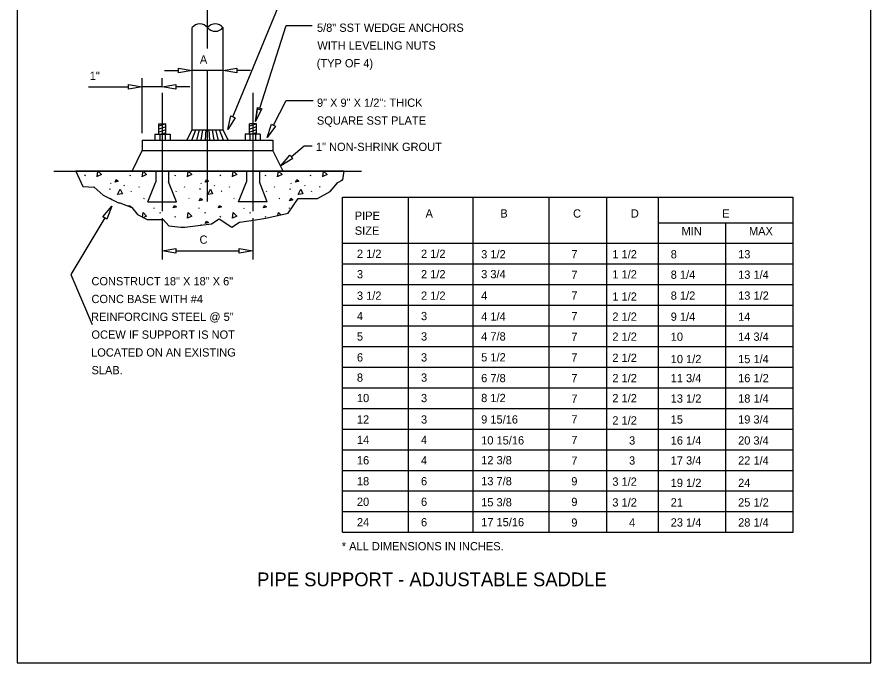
# Model space of a CAD drawing. Extents: x 2147138 to 2147698, y 2147153 to 2147515.
# Drawn here: x 2147297.9 to 2147422.1, y 2147351.3 to 2147445.1 of the extents above; entities that cross this region are included whole.
import ezdxf

# ---------------------------------------------------------------- set-up
doc = ezdxf.new("R2010")
doc.units = 0
for name, color, linetype in [('1', 7, 'Continuous'), ('D-PIPE-CNTR', 7, 'Continuous'), ('G-ANNO-TABL', 7, 'Continuous'), ('G-ANNO-TEXT-LW10', 7, 'Continuous'), ('G-ANNO-TITL', 7, 'Continuous'), ('G-DETL-HIDD', 7, 'Continuous'), ('G-DETL-LW10', 7, 'Continuous'), ('G-DETL-LW20', 7, 'Continuous'), ('G-DETL-PATT', 7, 'Continuous'), ('PATTERN_CLASS', 7, 'Continuous')]:
    doc.layers.add(name, color=color, linetype=linetype)

msp = doc.modelspace()

# ---------------------------------------------------------------- linework, layer by layer
at = {"layer": '1'}
for p, q in [((2147307.76, 2147422.09), (2147307.82, 2147422.23)), ((2147309.53, 2147421.94), (2147309.65, 2147422.77)), ((2147310.17, 2147422.24), (2147309.55, 2147421.95)), ((2147309.65, 2147422.77), (2147310.17, 2147422.24)), ((2147312.11, 2147422.69), (2147312.14, 2147422.77)), ((2147314.32, 2147422.09), (2147314.38, 2147422.23)), ((2147316.09, 2147421.94), (2147316.21, 2147422.77)), ((2147316.73, 2147422.24), (2147316.11, 2147421.95)), ((2147316.21, 2147422.77), (2147316.73, 2147422.24)), ((2147320.88, 2147422.09), (2147320.94, 2147422.23)), ((2147322.66, 2147421.94), (2147322.77, 2147422.77)), ((2147323.29, 2147422.24), (2147322.67, 2147421.95)), ((2147322.77, 2147422.77), (2147323.29, 2147422.24)), ((2147325.23, 2147422.69), (2147325.27, 2147422.77)), ((2147327.44, 2147422.09), (2147327.5, 2147422.23)), ((2147329.22, 2147421.94), (2147329.33, 2147422.77)), ((2147329.85, 2147422.24), (2147329.23, 2147421.95)), ((2147329.34, 2147422.77), (2147329.85, 2147422.24)), ((2147334.01, 2147422.09), (2147334.06, 2147422.23)), ((2147335.78, 2147421.94), (2147335.89, 2147422.77)), ((2147336.42, 2147422.24), (2147335.79, 2147421.95)), ((2147335.9, 2147422.77), (2147336.42, 2147422.24)), ((2147338.35, 2147422.69), (2147338.39, 2147422.77)), ((2147340.57, 2147422.09), (2147340.63, 2147422.23)), ((2147342.34, 2147421.94), (2147342.45, 2147422.77)), ((2147342.98, 2147422.24), (2147342.35, 2147421.95)), ((2147342.46, 2147422.77), (2147342.98, 2147422.24)), ((2147344.92, 2147422.69), (2147344.95, 2147422.77)), ((2147311.47, 2147421.06), (2147311.53, 2147420.97)), ((2147312.14, 2147421.16), (2147312.31, 2147421.53)), ((2147312.6, 2147421.31), (2147312.14, 2147421.16)), ((2147312.31, 2147421.53), (2147312.6, 2147421.31)), ((2147324.59, 2147421.06), (2147324.65, 2147420.97)), ((2147325.26, 2147421.16), (2147325.43, 2147421.53)), ((2147325.73, 2147421.31), (2147325.26, 2147421.16)), ((2147325.43, 2147421.53), (2147325.73, 2147421.31)), ((2147331.15, 2147421.06), (2147331.18, 2147421.03)), ((2147337.71, 2147421.06), (2147337.77, 2147420.97)), ((2147338.38, 2147421.16), (2147338.56, 2147421.53)), ((2147338.85, 2147421.31), (2147338.38, 2147421.16)), ((2147338.56, 2147421.53), (2147338.85, 2147421.31)), ((2147344.28, 2147421.06), (2147344.33, 2147420.97)), ((2147345.06, 2147421.4), (2147345.12, 2147421.53)), ((2147345.12, 2147421.53), (2147345.19, 2147421.47)), ((2147309.08, 2147420.41), (2147309.14, 2147420.54)), ((2147311.36, 2147420.1), (2147311.42, 2147420.23)), ((2147312.5, 2147419.37), (2147312.89, 2147420.12)), ((2147312.89, 2147420.12), (2147313.2, 2147419.43)), ((2147313.43, 2147420.69), (2147313.49, 2147420.6)), ((2147314.47, 2147419.77), (2147314.53, 2147419.9)), ((2147315.65, 2147420.41), (2147315.71, 2147420.54)), ((2147321.03, 2147419.77), (2147321.09, 2147419.9)), ((2147322.21, 2147420.41), (2147322.27, 2147420.54)), ((2147324.48, 2147420.1), (2147324.54, 2147420.23)), ((2147325.62, 2147419.37), (2147326.02, 2147420.12)), ((2147326.02, 2147420.12), (2147326.32, 2147419.43)), ((2147326.55, 2147420.69), (2147326.61, 2147420.6)), ((2147327.59, 2147419.77), (2147327.65, 2147419.9)), ((2147328.77, 2147420.41), (2147328.83, 2147420.54)), ((2147334.15, 2147419.77), (2147334.21, 2147419.9)), ((2147335.33, 2147420.41), (2147335.39, 2147420.54)), ((2147337.6, 2147420.1), (2147337.66, 2147420.23)), ((2147338.75, 2147419.37), (2147339.14, 2147420.12)), ((2147339.14, 2147420.12), (2147339.45, 2147419.43)), ((2147339.68, 2147420.69), (2147339.74, 2147420.6)), ((2147340.71, 2147419.77), (2147340.77, 2147419.9)), ((2147341.89, 2147420.41), (2147341.95, 2147420.54)), ((2147311.41, 2147418.77), (2147311.43, 2147418.82)), ((2147311.43, 2147418.82), (2147311.65, 2147418.65)), ((2147313.2, 2147419.43), (2147312.51, 2147419.37)), ((2147316.29, 2147418.83), (2147316.35, 2147418.75)), ((2147322.85, 2147418.83), (2147322.91, 2147418.75)), ((2147324.38, 2147418.45), (2147324.55, 2147418.82)), ((2147324.84, 2147418.6), (2147324.38, 2147418.45)), ((2147324.55, 2147418.82), (2147324.84, 2147418.6)), ((2147326.32, 2147419.43), (2147325.64, 2147419.37)), ((2147329.41, 2147418.83), (2147329.47, 2147418.75)), ((2147335.97, 2147418.83), (2147336.03, 2147418.75)), ((2147337.5, 2147418.45), (2147337.68, 2147418.82)), ((2147337.97, 2147418.6), (2147337.5, 2147418.45)), ((2147337.68, 2147418.82), (2147337.97, 2147418.6)), ((2147339.45, 2147419.43), (2147338.76, 2147419.37)), ((2147314.14, 2147417.63), (2147314.21, 2147417.78)), ((2147314.21, 2147417.78), (2147314.5, 2147417.56)), ((2147314.5, 2147417.56), (2147314.39, 2147417.52)), ((2147317.76, 2147417.44), (2147317.77, 2147417.31)), ((2147320.59, 2147417.41), (2147320.77, 2147417.78)), ((2147321.06, 2147417.56), (2147320.59, 2147417.41)), ((2147320.77, 2147417.78), (2147321.06, 2147417.56)), ((2147324.32, 2147417.44), (2147324.34, 2147417.31)), ((2147327.16, 2147417.41), (2147327.33, 2147417.78)), ((2147327.62, 2147417.56), (2147327.16, 2147417.41)), ((2147327.33, 2147417.78), (2147327.62, 2147417.56)), ((2147330.88, 2147417.44), (2147330.9, 2147417.31)), ((2147333.72, 2147417.41), (2147333.89, 2147417.78)), ((2147334.18, 2147417.56), (2147333.72, 2147417.41)), ((2147333.89, 2147417.78), (2147334.18, 2147417.56)), ((2147337.45, 2147417.44), (2147337.46, 2147417.31)), ((2147316.11, 2147416.07), (2147316.21, 2147416.75)), ((2147316.21, 2147416.75), (2147316.73, 2147416.21)), ((2147316.73, 2147416.21), (2147316.26, 2147415.99)), ((2147318.67, 2147416.66), (2147318.73, 2147416.79)), ((2147320.88, 2147416.07), (2147320.94, 2147416.2)), ((2147322.66, 2147415.92), (2147322.77, 2147416.75)), ((2147323.29, 2147416.21), (2147322.67, 2147415.92)), ((2147322.77, 2147416.75), (2147323.29, 2147416.21)), ((2147325.23, 2147416.66), (2147325.29, 2147416.79)), ((2147327.44, 2147416.07), (2147327.5, 2147416.2)), ((2147329.22, 2147415.92), (2147329.33, 2147416.75)), ((2147329.85, 2147416.21), (2147329.23, 2147415.92)), ((2147329.33, 2147416.75), (2147329.85, 2147416.21)), ((2147331.79, 2147416.66), (2147331.85, 2147416.79)), ((2147334.01, 2147416.07), (2147334.06, 2147416.2)), ((2147335.83, 2147416.31), (2147335.89, 2147416.75)), ((2147335.89, 2147416.75), (2147336.23, 2147416.4)), ((2147324.59, 2147415.03), (2147324.65, 2147414.94)), ((2147325.26, 2147415.13), (2147325.43, 2147415.5)), ((2147325.73, 2147415.28), (2147325.26, 2147415.13)), ((2147325.43, 2147415.5), (2147325.73, 2147415.28))]:
    msp.add_line(p, q, dxfattribs=at)
at = {"layer": 'D-PIPE-CNTR'}
for p, q in [((2147325.59, 2147440.58), (2147325.59, 2147449.16)), ((2147325.59, 2147418.35), (2147325.59, 2147437.38)), ((2147318.99, 2147434.15), (2147318.99, 2147416.93)), ((2147332.18, 2147434.15), (2147332.18, 2147416.93))]:
    msp.add_line(p, q, dxfattribs=at)
at = {"layer": 'G-ANNO-TABL'}
for p, q in [((2147345.2, 2147418.97), (2147410.75, 2147418.97)), ((2147345.2, 2147370.26), (2147345.2, 2147418.97)), ((2147354.81, 2147370.26), (2147354.81, 2147418.97)), ((2147364.23, 2147370.26), (2147364.23, 2147418.97)), ((2147375.25, 2147370.26), (2147375.25, 2147418.97)), ((2147383.65, 2147370.26), (2147383.65, 2147418.97)), ((2147391.15, 2147370.26), (2147391.15, 2147418.97)), ((2147410.75, 2147370.26), (2147410.75, 2147418.97)), ((2147391.15, 2147415.26), (2147410.75, 2147415.26)), ((2147345.2, 2147412.26), (2147410.75, 2147412.26)), ((2147345.2, 2147409.26), (2147410.75, 2147409.26)), ((2147345.2, 2147406.26), (2147410.75, 2147406.26)), ((2147345.2, 2147403.26), (2147410.75, 2147403.26)), ((2147345.2, 2147400.26), (2147410.75, 2147400.26)), ((2147345.2, 2147397.26), (2147410.75, 2147397.26)), ((2147345.2, 2147394.26), (2147410.75, 2147394.26)), ((2147345.2, 2147391.26), (2147410.75, 2147391.26)), ((2147345.2, 2147388.26), (2147410.75, 2147388.26)), ((2147345.2, 2147385.26), (2147410.75, 2147385.26)), ((2147345.2, 2147382.26), (2147410.75, 2147382.26)), ((2147345.2, 2147379.26), (2147410.75, 2147379.26)), ((2147345.2, 2147376.26), (2147410.75, 2147376.26)), ((2147345.2, 2147373.26), (2147410.75, 2147373.26)), ((2147345.2, 2147370.26), (2147410.75, 2147370.26))]:
    msp.add_line(p, q, dxfattribs=at)
at = {"layer": 'G-ANNO-TEXT-LW10'}
for p, q in [((2147329.28, 2147430.64), (2147337.01, 2147449.42)), ((2147333.17, 2147431.89), (2147337.01, 2147443.92)), ((2147337.01, 2147443.92), (2147340.78, 2147443.92)), ((2147319.34, 2147437.38), (2147321.34, 2147437.38)), ((2147327.84, 2147437.38), (2147323.34, 2147437.38)), ((2147331.84, 2147437.38), (2147329.84, 2147437.38)), ((2147316.1, 2147428.27), (2147316.1, 2147436.29)), ((2147318.99, 2147435.15), (2147318.99, 2147436.29)), ((2147308.25, 2147435.01), (2147314.1, 2147435.01)), ((2147318.99, 2147435.01), (2147316.1, 2147435.01)), ((2147322.99, 2147435.01), (2147320.99, 2147435.01)), ((2147335.16, 2147429.43), (2147337.01, 2147433.02)), ((2147337.01, 2147433.02), (2147340.97, 2147433.02)), ((2147337.76, 2147424.83), (2147339.63, 2147426.45)), ((2147339.63, 2147426.45), (2147340.79, 2147426.45)), ((2147310.65, 2147415.96), (2147305.68, 2147407.72)), ((2147318.99, 2147415.93), (2147318.99, 2147409.89)), ((2147332.18, 2147415.93), (2147332.18, 2147409.89)), ((2147400.95, 2147370.26), (2147400.95, 2147415.26)), ((2147320.99, 2147411.17), (2147330.18, 2147411.17)), ((2147305.68, 2147407.72), (2147308.81, 2147400.45))]:
    msp.add_line(p, q, dxfattribs=at)
for points in [[(2147321.34, 2147437.71), (2147323.34, 2147437.38), (2147321.34, 2147437.05)], [(2147329.84, 2147437.05), (2147327.84, 2147437.38), (2147329.84, 2147437.71)], [(2147314.1, 2147435.35), (2147316.1, 2147435.01), (2147314.1, 2147434.68)], [(2147320.99, 2147434.68), (2147318.99, 2147435.01), (2147320.99, 2147435.35)], [(2147329.59, 2147430.51), (2147328.52, 2147428.79), (2147328.97, 2147430.77)], [(2147333.49, 2147431.79), (2147332.56, 2147429.98), (2147332.85, 2147431.99)], [(2147333.39, 2147431.6), (2147332.82, 2147431.78), (2147332.56, 2147429.98)], [(2147335.46, 2147429.27), (2147334.25, 2147427.65), (2147334.87, 2147429.58)], [(2147337.98, 2147424.58), (2147336.25, 2147423.52), (2147337.54, 2147425.08)], [(2147310.37, 2147416.13), (2147311.68, 2147417.67), (2147310.94, 2147415.79)], [(2147320.99, 2147410.84), (2147318.99, 2147411.17), (2147320.99, 2147411.51)], [(2147330.18, 2147411.51), (2147332.18, 2147411.17), (2147330.18, 2147410.84)]]:
    msp.add_lwpolyline(points, close=True, dxfattribs=at)
at = {"layer": 'G-DETL-HIDD'}
for p, q in [((2147318.05, 2147422.77), (2147318.05, 2147421.21)), ((2147319.93, 2147422.77), (2147319.93, 2147421.21)), ((2147331.25, 2147422.77), (2147331.25, 2147421.21)), ((2147333.12, 2147422.77), (2147333.12, 2147421.21)), ((2147316.89, 2147418.29), (2147318.05, 2147421.21)), ((2147321.09, 2147418.29), (2147319.93, 2147421.21)), ((2147330.08, 2147418.29), (2147331.25, 2147421.21)), ((2147334.28, 2147418.29), (2147333.12, 2147421.21)), ((2147316.89, 2147418.29), (2147321.09, 2147418.29)), ((2147334.28, 2147418.29), (2147330.08, 2147418.29))]:
    msp.add_line(p, q, dxfattribs=at)
at = {"layer": 'G-DETL-LW10'}
for p, q in [((2147318.48, 2147428.12), (2147318.48, 2147429.61)), ((2147319.5, 2147429.61), (2147318.48, 2147429.29)), ((2147318.48, 2147429.61), (2147319.5, 2147429.61)), ((2147319.5, 2147428.12), (2147319.5, 2147429.61)), ((2147331.67, 2147428.12), (2147331.67, 2147429.61)), ((2147332.69, 2147429.61), (2147331.67, 2147429.61)), ((2147332.69, 2147429.61), (2147331.67, 2147429.29)), ((2147332.69, 2147428.12), (2147332.69, 2147429.61)), ((2147319.5, 2147429.18), (2147318.48, 2147428.86)), ((2147319.5, 2147428.76), (2147318.48, 2147428.44)), ((2147319.5, 2147428.33), (2147318.84, 2147428.12)), ((2147332.69, 2147429.18), (2147331.67, 2147428.86)), ((2147332.69, 2147428.76), (2147331.67, 2147428.44)), ((2147332.69, 2147428.33), (2147332.04, 2147428.12)), ((2147317.92, 2147428.12), (2147320.13, 2147428.12)), ((2147317.92, 2147428.12), (2147317.92, 2147427.27)), ((2147318.63, 2147428.12), (2147318.63, 2147427.27)), ((2147319.42, 2147428.12), (2147319.42, 2147427.27)), ((2147320.13, 2147428.12), (2147320.13, 2147427.27)), ((2147333.25, 2147428.12), (2147331.05, 2147428.12)), ((2147331.05, 2147428.12), (2147331.05, 2147427.27)), ((2147331.75, 2147428.12), (2147331.75, 2147427.27)), ((2147332.55, 2147428.12), (2147332.55, 2147427.27)), ((2147333.25, 2147428.12), (2147333.25, 2147427.27))]:
    msp.add_line(p, q, dxfattribs=at)
at = {"layer": 'G-DETL-LW20'}
for p, q in [((2147323.34, 2147428.77), (2147323.34, 2147443.62)), ((2147327.84, 2147428.77), (2147327.84, 2147443.62)), ((2147322.57, 2147427.27), (2147323.34, 2147428.77)), ((2147323.32, 2147427.27), (2147323.9, 2147428.77)), ((2147323.34, 2147428.77), (2147327.84, 2147428.77)), ((2147324.01, 2147427.27), (2147324.41, 2147428.77)), ((2147324.66, 2147427.27), (2147324.9, 2147428.77)), ((2147325.29, 2147427.27), (2147325.37, 2147428.77)), ((2147325.91, 2147427.27), (2147325.84, 2147428.77)), ((2147326.54, 2147427.27), (2147326.31, 2147428.77)), ((2147327.2, 2147427.27), (2147326.8, 2147428.77)), ((2147327.89, 2147427.27), (2147327.31, 2147428.77)), ((2147328.59, 2147427.27), (2147327.84, 2147428.77)), ((2147316.1, 2147427.27), (2147335.07, 2147427.27)), ((2147316.1, 2147427.27), (2147316.1, 2147425.77)), ((2147335.07, 2147427.27), (2147335.07, 2147425.77)), ((2147314.6, 2147422.77), (2147316.1, 2147425.77)), ((2147316.1, 2147425.77), (2147335.07, 2147425.77)), ((2147336.57, 2147422.77), (2147335.07, 2147425.77)), ((2147303.21, 2147422.77), (2147347.97, 2147422.77))]:
    msp.add_line(p, q, dxfattribs=at)
for centre, start, end in [((2147324.46, 2147442.73), 38.3518, 141.6482), ((2147326.71, 2147442.73), 38.3518, 141.6482), ((2147326.71, 2147444.51), 218.3518, 321.6482)]:
    msp.add_arc(centre, 1.43, start, end, dxfattribs=at)
at = {"layer": 'G-DETL-PATT'}
for p, q in [((2147306.44, 2147422.77), (2147307.45, 2147420.5)), ((2147345.47, 2147422.77), (2147306.44, 2147422.77)), ((2147306.44, 2147422.77), (2147306.44, 2147422.77)), ((2147345.26, 2147421.51), (2147345.47, 2147422.77)), ((2147343.43, 2147419.79), (2147344.55, 2147421.11)), ((2147344.55, 2147421.11), (2147345.26, 2147421.51)), ((2147307.45, 2147420.5), (2147309.08, 2147420.4)), ((2147309.08, 2147420.4), (2147310.4, 2147419.28)), ((2147341.6, 2147418.77), (2147343.43, 2147419.79)), ((2147310.4, 2147419.28), (2147312.64, 2147418.16)), ((2147337.33, 2147416.64), (2147338.76, 2147418.77)), ((2147338.76, 2147418.77), (2147341.6, 2147418.77)), ((2147312.64, 2147418.16), (2147312.84, 2147418.16)), ((2147312.84, 2147418.16), (2147314.57, 2147417.45)), ((2147314.57, 2147417.45), (2147315.38, 2147416.43)), ((2147315.38, 2147416.43), (2147316.8, 2147415.72)), ((2147332.25, 2147415.62), (2147334.08, 2147415.93)), ((2147334.08, 2147415.93), (2147337.33, 2147416.64)), ((2147316.8, 2147415.72), (2147319.14, 2147415.72)), ((2147319.14, 2147415.72), (2147319.95, 2147414.81)), ((2147319.95, 2147414.81), (2147321.68, 2147414.6)), ((2147322.29, 2147414.6), (2147326.15, 2147415.11)), ((2147326.15, 2147415.11), (2147327.27, 2147415.82)), ((2147327.27, 2147415.82), (2147329.1, 2147414.6)), ((2147329.1, 2147414.6), (2147330.22, 2147415.32)), ((2147330.22, 2147415.32), (2147332.25, 2147415.62)), ((2147321.68, 2147414.6), (2147322.29, 2147414.6))]:
    msp.add_line(p, q, dxfattribs=at)
for centre, start, end in [((2147326.71, 2147442.73), 38.3518, 141.6482), ((2147326.71, 2147444.51), 218.3518, 321.6482)]:
    msp.add_arc(centre, 1.43, start, end, dxfattribs=at)
at = {"layer": 'PATTERN_CLASS'}
for p, q in [((2147297.88, 2147503.54), (2147297.88, 2147351.27)), ((2147422.07, 2147351.27), (2147422.07, 2147503.54)), ((2147297.88, 2147351.27), (2147422.07, 2147351.27)), ((2147297.88, 2147351.27), (2147297.88, 2147351.27))]:
    msp.add_line(p, q, dxfattribs=at)

# ---------------------------------------------------------------- texts
at = {"layer": 'G-ANNO-TEXT-LW10'}
for s, p in [('5/8" SST WEDGE ANCHORS', (2147341.5, 2147443)), ('WITH LEVELING NUTS', (2147341.56, 2147440.41)), ('A', (2147324.47, 2147438.38)), ('(TYP OF 4)', (2147341.46, 2147437.83)), ('1"', (2147308.45, 2147436.02)), ('9" X 9" X 1/2": THICK', (2147341.5, 2147432.1)), ('SQUARE SST PLATE', (2147341.49, 2147429.51)), ('1" NON-SHRINK GROUT', (2147341.35, 2147425.68)), ('A', (2147357.29, 2147416)), ('B', (2147368.17, 2147416)), ('C', (2147378.75, 2147416)), ('D', (2147387.15, 2147416)), ('E', (2147400.44, 2147416)), ('PIPE', (2147347, 2147415.67)), ('SIZE', (2147347, 2147413.5)), ('MIN', (2147394.53, 2147413.43)), ('MAX', (2147404.33, 2147413.43)), ('C', (2147324.42, 2147412.2)), ('2 1/2', (2147347.31, 2147410.14)), ('2 1/2', (2147356.63, 2147410.14)), ('3 1/2', (2147365.38, 2147410.07)), ('7', (2147378.49, 2147410.07)), ('1 1/2', (2147384.46, 2147410.07)), ('8', (2147392.95, 2147410.07)), ('13', (2147402.75, 2147410.07)), ('2 1/2', (2147356.63, 2147407.17)), ('3 3/4', (2147365.38, 2147407.18)), ('1 1/2', (2147384.46, 2147407.15)), ('CONSTRUCT 18" X 18" X 6"', (2147308.7, 2147406.15)), ('3', (2147347.31, 2147407.17)), ('7', (2147378.49, 2147407.07)), ('8 1/4', (2147392.95, 2147407.1)), ('13 1/4', (2147402.75, 2147407.1)), ('CONC BASE WITH #4', (2147308.7, 2147403.57)), ('3 1/2', (2147347.31, 2147404.05)), ('2 1/2', (2147356.63, 2147404.05)), ('4', (2147365.38, 2147404.06)), ('7', (2147378.49, 2147404.07)), ('1 1/2', (2147384.46, 2147403.92)), ('8 1/2', (2147392.95, 2147404.06)), ('13 1/2', (2147402.75, 2147404.06)), ('REINFORCING STEEL @ 5"', (2147308.64, 2147400.98)), ('4', (2147347.31, 2147401.09)), ('3', (2147356.63, 2147401.09)), ('4 1/4', (2147365.38, 2147401.02)), ('7', (2147378.49, 2147401.07)), ('2 1/2', (2147384.46, 2147401)), ('9 1/4', (2147392.95, 2147401)), ('14', (2147402.75, 2147401)), ('OCEW IF SUPPORT IS NOT', (2147308.7, 2147398.39)), ('5', (2147347.31, 2147398.12)), ('3', (2147356.63, 2147398.12)), ('4 7/8', (2147365.38, 2147398.13)), ('7', (2147378.49, 2147398.07)), ('2 1/2', (2147384.46, 2147398.09)), ('10', (2147392.95, 2147398.09)), ('14 3/4', (2147402.75, 2147398.09)), ('LOCATED ON AN EXISTING', (2147308.65, 2147395.8)), ('6', (2147347.31, 2147395.08)), ('3', (2147356.63, 2147395.08)), ('5 1/2', (2147365.38, 2147395.09)), ('7', (2147378.49, 2147395.07)), ('2 1/2', (2147384.46, 2147395.02)), ('10 1/2', (2147392.95, 2147394.84)), ('15 1/4', (2147402.75, 2147394.84)), ('SLAB.', (2147308.71, 2147393.22)), ('8', (2147347.31, 2147392.14)), ('3', (2147356.63, 2147392.14)), ('6 7/8', (2147365.38, 2147392.07)), ('7', (2147378.49, 2147392.07)), ('2 1/2', (2147384.46, 2147392.07)), ('11 3/4', (2147392.95, 2147392.07)), ('16 1/2', (2147402.75, 2147392.07)), ('10', (2147347.31, 2147389.17)), ('3', (2147356.63, 2147389.17)), ('8 1/2', (2147365.38, 2147389.18)), ('7', (2147378.49, 2147389.07)), ('2 1/2', (2147384.46, 2147389.15)), ('13 1/2', (2147392.95, 2147389.1)), ('18 1/4', (2147402.75, 2147389.1)), ('9 15/16', (2147365.38, 2147386.06)), ('19 3/4', (2147402.75, 2147386.06)), ('12', (2147347.31, 2147386.05)), ('3', (2147356.63, 2147386.05)), ('7', (2147378.49, 2147386.07)), ('2 1/2', (2147384.46, 2147385.92)), ('15', (2147392.95, 2147386.06)), ('14', (2147347.31, 2147383.09)), ('4', (2147356.63, 2147383.09)), ('10 15/16', (2147365.38, 2147383.02)), ('7', (2147378.49, 2147383.07)), ('3', (2147386.89, 2147383)), ('16 1/4', (2147392.95, 2147383)), ('20 3/4', (2147402.75, 2147383)), ('16', (2147347.31, 2147380.12)), ('4', (2147356.63, 2147380.12)), ('12 3/8', (2147365.38, 2147380.13)), ('7', (2147378.49, 2147380.07)), ('3', (2147386.89, 2147380.09)), ('17 3/4', (2147392.95, 2147380.09)), ('22 1/4', (2147402.75, 2147380.09)), ('18', (2147347.31, 2147377.08)), ('6', (2147356.63, 2147377.08)), ('13 7/8', (2147365.38, 2147377.09)), ('9', (2147378.49, 2147377.07)), ('3 1/2', (2147384.46, 2147377.02)), ('19 1/2', (2147392.95, 2147376.84)), ('24', (2147402.75, 2147376.84)), ('20', (2147347.31, 2147374.09)), ('6', (2147356.63, 2147374.09)), ('15 3/8', (2147365.38, 2147374.02)), ('9', (2147378.49, 2147374.07)), ('3 1/2', (2147384.46, 2147374)), ('21', (2147392.95, 2147374)), ('25 1/2', (2147402.75, 2147374)), ('17 15/16', (2147365.38, 2147371.13)), ('24', (2147347.31, 2147371.12)), ('6', (2147356.63, 2147371.12)), ('9', (2147378.49, 2147371.07)), ('4', (2147386.89, 2147371.09)), ('23 1/4', (2147392.95, 2147371.09)), ('28 1/4', (2147402.75, 2147371.09)), ('* ALL DIMENSIONS IN INCHES.', (2147345.11, 2147367.63))]:
    msp.add_text(s, height=1.2, dxfattribs=at).set_placement(p)
at = {"layer": 'G-ANNO-TITL'}
msp.add_text('PIPE SUPPORT - ADJUSTABLE SADDLE', height=2, dxfattribs=at).set_placement((2147332.8, 2147362.41))

doc.saveas('drawing.dxf')
